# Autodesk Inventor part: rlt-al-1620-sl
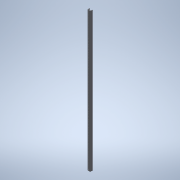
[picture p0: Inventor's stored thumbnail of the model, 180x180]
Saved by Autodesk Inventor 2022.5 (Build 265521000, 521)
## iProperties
Created: 2016-12
Part Number: rlt-al-1620-sl
Material: 一般
Document SubType Name: Modeling
Designer: imaocorp
Density: 1 g/cm^3
Appearance: 既定
Author: imaocorp
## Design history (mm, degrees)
node "rlt-al-1620-sl.x_t1"
node "rlt-al-1620-sl"
node "Base1"
